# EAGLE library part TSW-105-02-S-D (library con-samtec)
THROUGH-HOLE .025" SQ POST HEADER Source: Samtec TSW.pdf
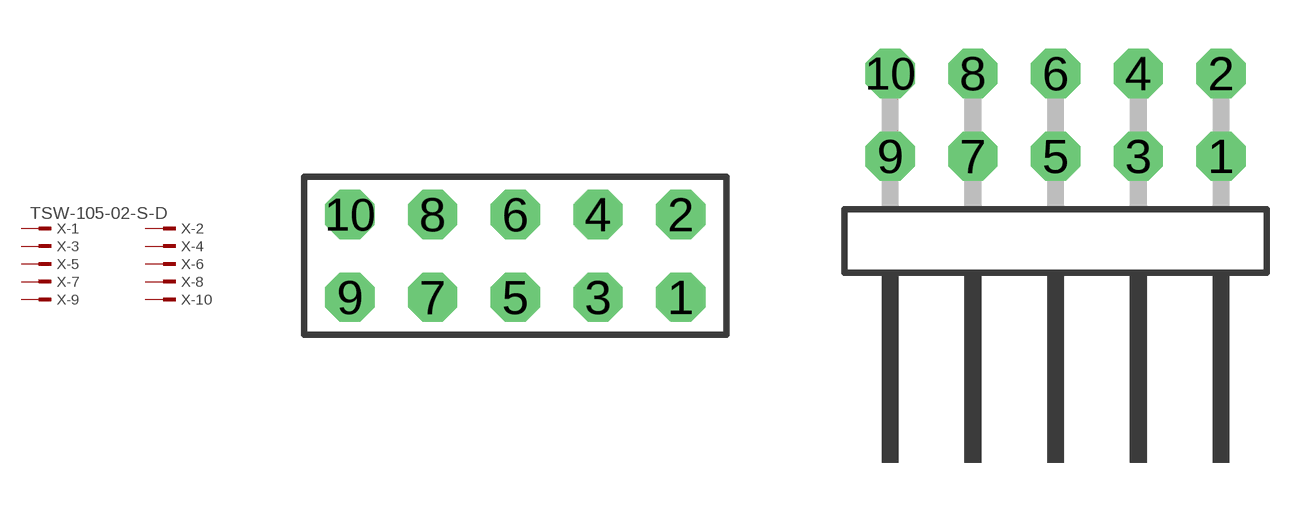
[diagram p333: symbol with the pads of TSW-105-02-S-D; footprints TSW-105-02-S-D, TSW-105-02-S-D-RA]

Designator prefix X; gates -1=MPINV -2=MPIN -3=MPIN -4=MPIN -5=MPIN -6=MPIN -7=MPIN -8=MPIN -9=MPIN -10=MPIN

## TSW-105-02-S-D (OC_FARNELL: unknown; OC_NEWARK: unknown)  [TSW-105-02-S-D]
1  -1:1  pas
2  -2:1  pas
3  -3:1  pas
4  -4:1  pas
5  -5:1  pas
6  -6:1  pas
7  -7:1  pas
8  -8:1  pas
9  -9:1  pas
10  -10:1  pas

## TSW-105-02-S-D-RA (OC_FARNELL: unknown; OC_NEWARK: unknown)  [TSW-105-02-S-D-RA]
Pads as for TSW-105-02-S-D

## Footprint TSW-105-02-S-D (pad centres in mm)
THROUGH-HOLE .025" SQ POST HEADER Source: Samtec TSW.pdf
drill 1 pad 1.5 octagon: 1 5.08,-1.27; 2 5.08,1.27; 3 2.54,-1.27; 4 2.54,1.27; 5 0,-1.27; 6 0,1.27; 7 -2.54,-1.27; 8 -2.54,1.27; 9 -5.08,-1.27; 10 -5.08,1.27

## Footprint TSW-105-02-S-D-RA (pad centres in mm)
THROUGH-HOLE .025" SQ POST HEADER Source: Samtec TSW.pdf
drill 1 pad 1.5 octagon: 1 5.08,1.524; 2 5.08,4.064; 3 2.54,1.524; 4 2.54,4.064; 5 0,1.524; 6 0,4.064; 7 -2.54,1.524; 8 -2.54,4.064; 9 -5.08,1.524; 10 -5.08,4.064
